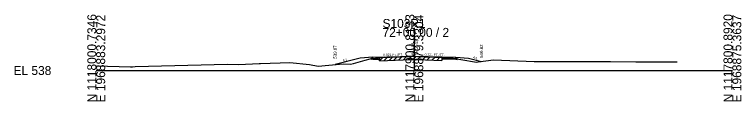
# Model space of a CAD drawing. Extents: x -26 to 203, y -10 to 12018.
# Drawn here: x -25.7 to 202.8, y 9990.3 to 10017.5 of the extents above; entities that cross this region are included whole.
import ezdxf

# ---------------------------------------------------------------- set-up
doc = ezdxf.new("R2010")
doc.units = 0
for name, color, linetype in [('Level 10', 7, 'Continuous'), ('Level 11', 7, 'Continuous'), ('Level 12', 7, 'Continuous'), ('Level 32', 7, 'Continuous'), ('Level 33', 7, 'Continuous'), ('Level 59', 7, 'Continuous'), ('Level 6', 7, 'Continuous'), ('Level 60', 7, 'Continuous'), ('Level 61', 7, 'Continuous'), ('Level 63', 7, 'Continuous'), ('Level 7', 7, 'Continuous')]:
    doc.layers.add(name, color=color, linetype=linetype)

msp = doc.modelspace()

# ---------------------------------------------------------------- linework, layer by layer
at = {"layer": 'Level 11'}
for p, q in [((86.5, 10003.86), (87, 10003.87)), ((86.5, 10003.5), (86.5, 10003.86)), ((87, 10003.51), (86.5, 10003.5)), ((87, 10003.87), (87, 10004.18)), ((113, 10003.87), (113, 10004.18)), ((113.5, 10003.86), (113, 10003.87)), ((113, 10003.51), (113.5, 10003.5)), ((113.5, 10003.5), (113.5, 10003.86))]:
    msp.add_line(p, q, dxfattribs=at)
at = {"layer": 'Level 12'}
for p, q in [((87, 10003.51), (89.04, 10003.55)), ((89.04, 10004.05), (89.04, 10003.55)), ((108.68, 10004.12), (108.68, 10003.6)), ((113, 10003.51), (108.68, 10003.6))]:
    msp.add_line(p, q, dxfattribs=at)
at = {"layer": 'Level 59'}
for p, q in [((87, 10004.18), (100, 10004.45)), ((100, 10004.45), (113, 10004.18))]:
    msp.add_line(p, q, dxfattribs=at)
at = {"layer": 'Level 6'}
for p, q in [((87, 10004.18), (83, 10003.85)), ((113, 10004.18), (117, 10003.85))]:
    msp.add_line(p, q, dxfattribs=at)
at = {"layer": 'Level 60'}
for p, q in [((80.82, 10002.17), (84.54, 10003.2)), ((84.54, 10003.2), (86.07, 10003.62)), ((86.07, 10003.62), (88.61, 10003.99)), ((88.61, 10003.99), (89.04, 10004.05)), ((89.04, 10004.05), (98.98, 10004.41)), ((98.98, 10004.41), (100.11, 10004.45)), ((100.11, 10004.45), (100.97, 10004.42)), ((100.97, 10004.42), (108.68, 10004.12)), ((108.68, 10004.12), (108.98, 10004.11)), ((108.98, 10004.11), (111.57, 10003.95)), ((111.57, 10003.95), (118.95, 10002.75)), ((120.04, 10002.69), (124.84, 10003.3)), ((124.84, 10003.3), (137.69, 10002.78)), ((0, 10001.44), (10.81, 10001.19)), ((10.81, 10001.19), (11.35, 10001.18)), ((11.35, 10001.18), (12.18, 10001.22)), ((12.18, 10001.22), (41.21, 10002.03)), ((41.21, 10002.03), (44.86, 10001.84)), ((44.86, 10001.84), (51.25, 10002.17)), ((51.25, 10002.17), (51.64, 10002.19)), ((51.64, 10002.19), (60.81, 10002.5)), ((60.81, 10002.5), (67.07, 10001.92)), ((67.07, 10001.92), (69.76, 10001.37)), ((69.76, 10001.37), (77.64, 10002.1)), ((77.64, 10002.1), (79.9, 10001.96)), ((79.9, 10001.96), (80.82, 10002.17)), ((118.95, 10002.75), (119.63, 10002.63)), ((119.63, 10002.63), (120.04, 10002.69)), ((137.69, 10002.78), (161.63, 10002.83)), ((161.63, 10002.83), (169.6, 10002.73)), ((169.6, 10002.73), (182.63, 10002.68))]:
    msp.add_line(p, q, dxfattribs=at)
at = {"layer": 'Level 61'}
for p, q in [((89.04, 10003.05), (90.08, 10004.08)), ((89.04, 10003.05), (89.04, 10004.05)), ((89.04, 10003.05), (98.98, 10003.41)), ((90.54, 10003.1), (91.58, 10004.14)), ((92.04, 10003.16), (93.08, 10004.2)), ((93.54, 10003.21), (94.58, 10004.25)), ((95.04, 10003.27), (96.08, 10004.31)), ((96.54, 10003.32), (97.58, 10004.36)), ((98.04, 10003.38), (99.08, 10004.42)), ((98.98, 10003.41), (100.11, 10003.45)), ((99.54, 10003.43), (100.54, 10004.44)), ((100.11, 10003.45), (100.97, 10003.42)), ((100.97, 10003.42), (108.68, 10003.12)), ((101.04, 10003.42), (102, 10004.38)), ((102.54, 10003.36), (103.5, 10004.32)), ((104.04, 10003.3), (105, 10004.27)), ((105.54, 10003.24), (106.5, 10004.21)), ((107.04, 10003.19), (108, 10004.15)), ((108.68, 10004.12), (108.68, 10003.12))]:
    msp.add_line(p, q, dxfattribs=at)
at = {"layer": 'Level 63'}
for p, q in [((100, 10000), (100, 10013.36)), ((0, 10000), (100, 10000)), ((100, 10000), (200, 10000))]:
    msp.add_line(p, q, dxfattribs=at)
at = {"layer": 'Level 7'}
for p, q in [((83, 10003.85), (75.08, 10001.87)), ((117, 10003.85), (121.1, 10002.82))]:
    msp.add_line(p, q, dxfattribs=at)

# ---------------------------------------------------------------- texts
at = {"layer": 'Level 10'}
msp.add_text(' 542.58', height=0.9, rotation=90, dxfattribs=at).set_placement((99.95, 10004.59))
at = {"layer": 'Level 32'}
for s, rotation, p in [('0.021 FT./FT.', 1.1916, (90.21, 10004.5)), ('0.021 FT./FT.', 358.8084, (103.22, 10004.63)), ('4:1', 14.0362, (77.57, 10002.73)), ('4:1', 345.9638, (118.39, 10003.82))]:
    msp.add_text(s, height=0.75, rotation=rotation, dxfattribs=at).set_placement(p)
at = {"layer": 'Level 33'}
for s, p in [('539.87', (75.58, 10003.69)), ('540.82', (121.6, 10003.94))]:
    msp.add_text(s, height=1, rotation=90, dxfattribs=at).set_placement(p)
at = {"layer": 'Level 59'}
msp.add_text(' 542.45', height=1.2, rotation=90, dxfattribs=at).set_placement((101.2, 10004.45))
at = {"layer": 'Level 63'}
for s, p in [('N 1118000.7346', (0, 9990)), ('E 1968883.2972', (2.8, 9990)), ('N 1117900.8133', (100, 9990)), ('E 1968879.3304', (102.8, 9990)), ('N 1117800.8920', (200, 9990)), ('E 1968875.3637', (202.8, 9990))]:
    msp.add_text(s, height=2.8, rotation=90, dxfattribs=at).set_placement(p)
for s, p in [('S103R1', (90, 10013.36)), ('72+00.00 / 2', (90, 10010.56)), ('EL 538', (-26, 9998.6))]:
    msp.add_text(s, height=2.8, dxfattribs=at).set_placement(p)

doc.saveas('drawing.dxf')
